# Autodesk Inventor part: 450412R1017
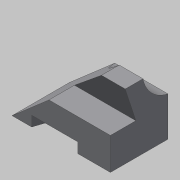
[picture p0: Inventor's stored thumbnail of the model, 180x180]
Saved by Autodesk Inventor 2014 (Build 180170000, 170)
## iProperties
Created: 2015-04
Part Number: 450412R1017
Material: Generic
Document SubType Name: Modeling
Designer: 203-12
Density: 1 g/cm^3
Appearance: Default
Author: 203-12
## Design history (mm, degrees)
sketch "스케치3"
  geometry: L1 (-67.5, 0)-(67.5, 0); L2 (67.5, 0)-(67.5, 79); L3 (67.5, 79)-(-67.5, 79); L4 (-67.5, 79)-(-67.5, 0); 2 further points
  constraints: 8 end point, 2 parallel, 1 coincident, 1 horizontal, 1 midpoint, 1 perpendicular
  dimensions: "d6" = 135 distance of L2.end L3.end; "d7" = 79 distance of L1.end L2.end
extrude "돌출1" new body sketch "스케치3" distance "d8" = 89; taper "d9" = 0 deg
sketch "스케치4"
  geometry: L1 (0, 0)-(135, 0) reference; L2 (0, 89)-(135, 89) reference; L3 (0, 0)-(0, 89) reference; L4 (0, 0)-(102.383, 89); 1 further point
  constraints: 2 end point, 1 point on line
  dimensions: "d10" = 139 deg angle of L1 L4
extrude "돌출2" cut sketch "스케치4" distance "d11" = 89; taper "d12" = 0 deg
sketch "스케치5"
  geometry: L1 (-67.5, 79)-(-67.5, 0) reference; L2 (-67.5, 0)-(67.5, 0) reference; L3 (67.5, 0)-(67.5, 79) reference; L4 (-40.5, 0)-(-14.831, 79); L5 (22.588, 0)-(48.256, 79); L6 (67.5, 79)-(-67.5, 79) reference; 1 further point
  constraints: 4 end point, 4 point on line, 1 parallel
  dimensions: "d13" = 60 distance between parallel lines of L5 L4; "d14" = 27 distance of L4.start L1.end; "d16" = 72 deg angle of L5 L6
extrude "돌출3" cut sketch "스케치5" distance "d17" = 14; taper "d18" = 0 deg
sketch "스케치6"
  geometry: L1 (0, 79)-(-89, 79) reference; L2 (-89, 0)-(-89, 79) reference; A1 r 44 centre (-97, 88) between (-89, 44.733) and (-53.93, 79)
  constraints: 2 point on circle, 2 point on line, 1 centre point
  dimensions: "d19" = 88 diameter of A1; "d20" = 9 distance from line of L1 A1.centre; "d21" = 8 distance from line of L2 A1.centre
extrude "돌출4" cut sketch "스케치6" stored distance "d22" = 14; taper "d23" = 0 deg
sketch "스케치7"
  geometry: L1 (-89, 0)-(-89, 44.733) reference; L2 (0, 0)-(-89, 0) reference; L3 (0, 0)-(0, 79) reference; L4 (0, 79)-(-53.93, 79) reference; L5 (-44, 0)-(-44, 35); L6 (-44, 35)-(-89, 20.379)
  constraints: 4 end point, 2 point on line, 1 perpendicular
  dimensions: "d24" = 44 distance between parallel lines of L3 L5; "d25" = 72 deg angle of L6 L5; "d26" = 35 distance of L5.start L5.end
extrude "돌출5" cut sketch "스케치7" stored distance "d27" = 14; taper "d28" = 0 deg
node "솔리드1"
